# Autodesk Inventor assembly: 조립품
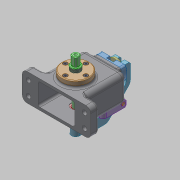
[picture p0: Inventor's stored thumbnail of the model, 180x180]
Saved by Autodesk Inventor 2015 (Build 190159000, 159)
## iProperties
Created: 2023-12
Part Number: 조립품
Document SubType Name: Assembly
Designer: 10415
Author: 10415
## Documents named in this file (14)
- C:\Users\10415\Desktop\731208V1013\조립품.iam
- C:\Users\10415\Desktop\731208V1013\본체.ipt
- C:\Users\10415\Desktop\731208V1013\가공품.ipt
- C:\Users\10415\Desktop\731208V1013\가이드 부시.ipt
- C:\Users\10415\Desktop\731208V1013\고정대.ipt
- C:\Users\10415\Desktop\731208V1013\브라켓.ipt
- C:\Users\10415\Desktop\731208V1013\스프링.ipt
- C:\Users\10415\Desktop\731208V1013\육각 머리 볼트 M6 x 12.ipt
- C:\Users\10415\Desktop\731208V1013\육각 소켓 머리 볼트 M3 x 8.ipt
- C:\Users\10415\Desktop\731208V1013\육각 소켓 머리 볼트 M3 x 30.ipt
- C:\Users\10415\Desktop\731208V1013\조절 부시.ipt
- C:\Users\10415\Desktop\731208V1013\클램프 샤프트.ipt
- C:\Users\10415\Desktop\731208V1013\클램프.ipt
- C:\Users\10415\Desktop\731208V1013\핀.ipt
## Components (4 placed, 4 different names)
1. 가공품:1 — 각도:1
2. 가이드 부시:1
3. 고정대:1
4. 핀:1 — 플러쉬:1
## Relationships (2: Flush 1, Angle 1)
- 플러쉬:1 [Flush]: 핀:1
- 각도:1 [Angle]: 가공품:1
